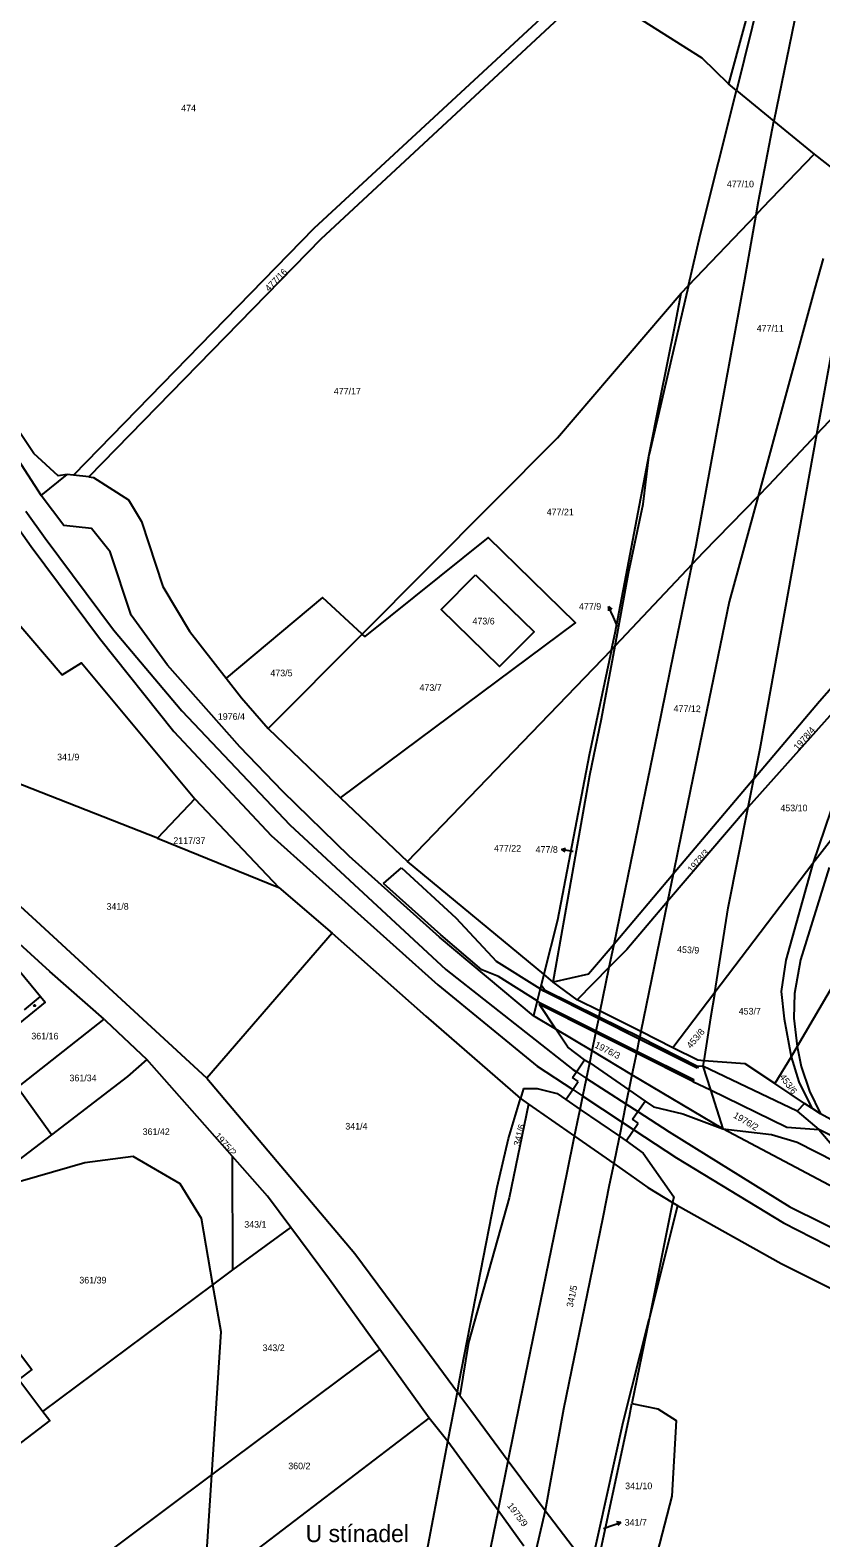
# Model space of a CAD drawing. Extents: x -679220 to -673243, y -1075091 to -1066557.
# Drawn here: x -675598.1 to -675395.3, y -1072555.7 to -1072169.3 of the extents above; entities that cross this region are included whole.
import ezdxf

# ---------------------------------------------------------------- set-up
doc = ezdxf.new("R2010")
doc.units = 0
for name, color, linetype in [('Hranice parcel', 7, 'Continuous'), ('Parcelní čísla', 7, 'Continuous'), ('Pop  PČ popisy', 7, 'Continuous'), ('Poz předměty', 7, 'Continuous'), ('Vnitřní kresba', 7, 'Continuous'), ('Značky budov', 7, 'Continuous')]:
    doc.layers.add(name, color=color, linetype=linetype)

msp = doc.modelspace()

# ---------------------------------------------------------------- linework, layer by layer
at = {"layer": 'Hranice parcel'}
for p, q in [((-675416.99, -1072184.77), (-675419.02, -1072183.11)), ((-675431.11, -1072236.72), (-675429.24, -1072234.77)), ((-675595.28, -1072288.62), (-675588.59, -1072283.25)), ((-675586.94, -1072283.42), (-675588.59, -1072283.25)), ((-675582.99, -1072283.84), (-675586.94, -1072283.42)), ((-675537.03, -1072348.31), (-675512.94, -1072324.1)), ((-675448.03, -1072327.12), (-675449.01, -1072328.16)), ((-675501.33, -1072382.38), (-675449.01, -1072328.16)), ((-675379.42, -1072329.8), (-675413.96, -1072368.46)), ((-675379.42, -1072329.8), (-675397.36, -1072382.87)), ((-675565.38, -1072376.43), (-675634.57, -1072349.32)), ((-675537.03, -1072348.31), (-675518.46, -1072366.07)), ((-675413.96, -1072368.46), (-675412.53, -1072361.24)), ((-675555.87, -1072366.37), (-675565.38, -1072376.43)), ((-675555.87, -1072366.37), (-675534.31, -1072389.02)), ((-675518.46, -1072366.07), (-675501.33, -1072382.38)), ((-675565.38, -1072376.43), (-675534.31, -1072389.02)), ((-675466.34, -1072411.3), (-675501.33, -1072382.38)), ((-675397.36, -1072382.87), (-675422.55, -1072416)), ((-675534.31, -1072389.02), (-675520.61, -1072400.73)), ((-675520.61, -1072400.73), (-675552.78, -1072437.9)), ((-675464, -1072413.32), (-675466.34, -1072411.3)), ((-675457.77, -1072417.82), (-675464, -1072413.32)), ((-675422.55, -1072416), (-675433.24, -1072430.14)), ((-675601.34, -1072440.3), (-675579.08, -1072422.85)), ((-675546.21, -1072458), (-675568.18, -1072433.16)), ((-675402.97, -1072432.45), (-675407.15, -1072439.33)), ((-675399.54, -1072444.38), (-675407.15, -1072439.33)), ((-675592.6, -1072452.44), (-675601.34, -1072440.3)), ((-675472.35, -1072443.11), (-675470.27, -1072444.57)), ((-675397.67, -1072445.61), (-675399.54, -1072444.38)), ((-675592.6, -1072452.44), (-675612.87, -1072467.95)), ((-675546.11, -1072487.08), (-675546.21, -1072458)), ((-675432.05, -1072470.56), (-675439.38, -1072499.72)), ((-675546.11, -1072487.08), (-675531.24, -1072476.19)), ((-675551.2, -1072490.89), (-675546.11, -1072487.08)), ((-675594.8, -1072523.34), (-675551.2, -1072490.89)), ((-675439.38, -1072499.72), (-675443.75, -1072521.35)), ((-675551.48, -1072539.61), (-675508.42, -1072507.49)), ((-675495.78, -1072525.1), (-675508.42, -1072507.49)), ((-675490.93, -1072531.03), (-675488.53, -1072518.4)), ((-675487.9, -1072519.25), (-675488.53, -1072518.4)), ((-675443.75, -1072521.35), (-675437.14, -1072522.7)), ((-675553.38, -1072569.02), (-675495.78, -1072525.1)), ((-675490.93, -1072531.03), (-675495.78, -1072525.1)), ((-675553.38, -1072569.02), (-675551.48, -1072539.61))]:
    msp.add_line(p, q, dxfattribs=at)
for points in [[(-675734.17, -1071838.14), (-675727.92, -1071869.06), (-675703.55, -1071993.04), (-675690.45, -1072058.85), (-675676.8, -1072118.37), (-675666.48, -1072149.75), (-675655.92, -1072177.48), (-675644.67, -1072202.06), (-675627.82, -1072234.57), (-675609.97, -1072265.91), (-675595.28, -1072288.62)], [(-675396.43, -1072100.9), (-675399.9, -1072112.67), (-675419.02, -1072183.11)], [(-675461.51, -1072161.01), (-675525.35, -1072220.15), (-675586.94, -1072283.42)], [(-675455.31, -1072159.46), (-675523.57, -1072222.93), (-675582.99, -1072283.84)], [(-675419.02, -1072183.11), (-675425.75, -1072176.54), (-675442.66, -1072165.78), (-675455.31, -1072159.46)], [(-675429.24, -1072234.77), (-675426.15, -1072221.5), (-675416.99, -1072184.77)], [(-675416.99, -1072184.77), (-675407.35, -1072192.65), (-675397.04, -1072201.08)], [(-675429.24, -1072234.77), (-675411.94, -1072216.66), (-675410.26, -1072214.9), (-675397.04, -1072201.08)], [(-675397.04, -1072201.08), (-675387.67, -1072208.44), (-675385.83, -1072210), (-675381.09, -1072214.03)], [(-675588.59, -1072283.25), (-675590.86, -1072283.57), (-675597.09, -1072277.84), (-675606.59, -1072263.7), (-675624.31, -1072232.74), (-675636.9, -1072208.76)], [(-675381.09, -1072214.03), (-675385.95, -1072219.83), (-675388.33, -1072228.27), (-675396.42, -1072272.96)], [(-675358.84, -1072232.94), (-675385.17, -1072261.11), (-675396.42, -1072272.96)], [(-675512.94, -1072324.1), (-675462.89, -1072273.79), (-675431.11, -1072236.72)], [(-675439.34, -1072278.05), (-675436.63, -1072264.33), (-675432.63, -1072244.42), (-675431.11, -1072236.72)], [(-675396.42, -1072272.96), (-675408.79, -1072286), (-675411.44, -1072288.72), (-675425.54, -1072303.22), (-675428.31, -1072306.15), (-675448.03, -1072327.12)], [(-675396.42, -1072272.96), (-675411, -1072353.53), (-675412.53, -1072361.24)], [(-675449.01, -1072328.16), (-675448.08, -1072323.76), (-675439.34, -1072278.05)], [(-675448.03, -1072327.12), (-675444.65, -1072308.47), (-675440.87, -1072290.79), (-675439.34, -1072278.05)], [(-675582.99, -1072283.84), (-675581.79, -1072283.97), (-675572.82, -1072289.71), (-675569.53, -1072295.25), (-675564.07, -1072311.9), (-675557.23, -1072323.34), (-675547.81, -1072335.42)], [(-675469.01, -1072421.97), (-675493.12, -1072401.8), (-675516.24, -1072381.02), (-675533.31, -1072364.43), (-675544.32, -1072352.97), (-675562.86, -1072332.04), (-675572.15, -1072319.29), (-675577.54, -1072303.06), (-675582.29, -1072297.06), (-675589.45, -1072296.26), (-675595.28, -1072288.62)], [(-675518.46, -1072366.07), (-675458.25, -1072321.24), (-675480.64, -1072299.39), (-675512.25, -1072324.74), (-675512.94, -1072324.1)], [(-675483.86, -1072308.92), (-675468.87, -1072323.55), (-675477.72, -1072332.44), (-675492.67, -1072317.81), (-675483.86, -1072308.92)], [(-675606.52, -1072315.16), (-675589.88, -1072334.57), (-675584.91, -1072331.48), (-675555.87, -1072366.37)], [(-675512.94, -1072324.1), (-675523.07, -1072314.75), (-675547.81, -1072335.42)], [(-675412.53, -1072361.24), (-675395.68, -1072341.32), (-675375.49, -1072318.41)], [(-675464, -1072413.32), (-675458.73, -1072383.94), (-675454.54, -1072360.24), (-675451.61, -1072345.79), (-675448.03, -1072327.12)], [(-675449.01, -1072328.16), (-675454.73, -1072355.18), (-675462.88, -1072397.47), (-675466.34, -1072411.3)], [(-675547.81, -1072335.42), (-675543.88, -1072340.45), (-675537.03, -1072348.31)], [(-675359.05, -1072336.81), (-675367.17, -1072346.12), (-675382.04, -1072363.17), (-675387.58, -1072370.29), (-675397.36, -1072382.87)], [(-675412.53, -1072361.24), (-675433.18, -1072385.64), (-675448.35, -1072403.57), (-675454.87, -1072411.28), (-675464, -1072413.32)], [(-675552.78, -1072437.9), (-675596.45, -1072397.73), (-675630.17, -1072366.89)], [(-675413.96, -1072368.46), (-675434.62, -1072392.65), (-675445.1, -1072404.93), (-675449.57, -1072409.47), (-675457.77, -1072417.82)], [(-675422.55, -1072416), (-675419.08, -1072394.3), (-675413.96, -1072368.46)], [(-675397.36, -1072382.87), (-675404.31, -1072407.7), (-675405.48, -1072415.72), (-675404.76, -1072422.71), (-675402.97, -1072432.45)], [(-675520.61, -1072400.73), (-675496.57, -1072422.06), (-675472.35, -1072443.11)], [(-675579.08, -1072422.85), (-675593.02, -1072410.6), (-675600.77, -1072403.5)], [(-675383.87, -1072402.76), (-675390.15, -1072411.15), (-675391.78, -1072413.33), (-675401.43, -1072429.83), (-675402.97, -1072432.45)], [(-675602.94, -1072425.54), (-675610.49, -1072416.34), (-675607.77, -1072414.09), (-675609.09, -1072412.5), (-675605.87, -1072409.85), (-675603.11, -1072407.59), (-675601.79, -1072409.24), (-675595.41, -1072416.98), (-675594.19, -1072418.46), (-675598.41, -1072421.88), (-675602.94, -1072425.54)], [(-675466.34, -1072411.3), (-675467.05, -1072414.13), (-675467.28, -1072415.07), (-675468.04, -1072418.11), (-675469.01, -1072421.97)], [(-675422.55, -1072416), (-675423.58, -1072422.44), (-675425.32, -1072433.45)], [(-675433.24, -1072430.14), (-675441.49, -1072426), (-675451.89, -1072420.77), (-675457.77, -1072417.82)], [(-675579.08, -1072422.85), (-675578.69, -1072423.2), (-675568.18, -1072433.16)], [(-675420.5, -1072450.92), (-675443.76, -1072437.04), (-675453.98, -1072430.94), (-675463.29, -1072425.38), (-675469.01, -1072421.97)], [(-675425.32, -1072433.45), (-675426.9, -1072433.33), (-675433.24, -1072430.14)], [(-675568.18, -1072433.16), (-675573.07, -1072437.5), (-675592.6, -1072452.44)], [(-675425.32, -1072433.45), (-675425.55, -1072434.88), (-675423.65, -1072440.93), (-675420.5, -1072450.92)], [(-675407.15, -1072439.33), (-675414.75, -1072434.28), (-675425.32, -1072433.45)], [(-675402.97, -1072432.45), (-675400.93, -1072438.84), (-675397.67, -1072445.61)], [(-675552.78, -1072437.9), (-675514.82, -1072482.88), (-675496.88, -1072507.03), (-675488.53, -1072518.4)], [(-675488.53, -1072518.4), (-675488.04, -1072515.8), (-675478.35, -1072465.86), (-675475.43, -1072453.36), (-675472.35, -1072443.11)], [(-675470.27, -1072444.57), (-675475.25, -1072468.57), (-675485.69, -1072505.71), (-675487.9, -1072519.25)], [(-675470.27, -1072444.57), (-675458.46, -1072452.81), (-675448.42, -1072459.82), (-675439.69, -1072465.91), (-675433.33, -1072469.79), (-675432.05, -1072470.56)], [(-675399.54, -1072444.38), (-675401.42, -1072446.36), (-675395.88, -1072451.08), (-675386.77, -1072461.8), (-675376.04, -1072474.42)], [(-675368.49, -1072461.75), (-675395.42, -1072447.1), (-675397.67, -1072445.61)], [(-675376.04, -1072474.42), (-675393.22, -1072465.39), (-675420.5, -1072450.92)], [(-675551.2, -1072490.89), (-675554.17, -1072473.86), (-675559.59, -1072465.02), (-675571.66, -1072458.04), (-675584, -1072459.65), (-675612.87, -1072467.95)], [(-675531.24, -1072476.19), (-675537.19, -1072468.19), (-675546.21, -1072458)], [(-675432.05, -1072470.56), (-675405.5, -1072485.44), (-675369.37, -1072503.53), (-675276.78, -1072545.83)], [(-675508.42, -1072507.49), (-675521.3, -1072489.55), (-675531.24, -1072476.19)], [(-675667.06, -1072576), (-675695.35, -1072538.98), (-675624.32, -1072484.68), (-675612.98, -1072499.47), (-675609.59, -1072496.88), (-675597.62, -1072512.63), (-675601, -1072515.19), (-675594.8, -1072523.34)], [(-675551.48, -1072539.61), (-675549.11, -1072502.92), (-675551.2, -1072490.89)], [(-675454.36, -1072563.91), (-675446, -1072526.06), (-675439.38, -1072499.72)], [(-675487.9, -1072519.25), (-675485.11, -1072523), (-675475.5, -1072535.97), (-675466.02, -1072548.77), (-675454.36, -1072563.91)], [(-675594.8, -1072523.34), (-675593.03, -1072525.66), (-675664.03, -1072579.96), (-675667.06, -1072576)], [(-675453.16, -1072565.56), (-675444.4, -1072524.55), (-675443.75, -1072521.35)], [(-675437.14, -1072522.7), (-675432.4, -1072525.63), (-675433.53, -1072545.05), (-675440.45, -1072571.81)], [(-675499.44, -1072577.56), (-675497.51, -1072565.78), (-675490.93, -1072531.03)], [(-675471.44, -1072557.92), (-675478.09, -1072548.74), (-675490.93, -1072531.03)], [(-675681.36, -1072633.74), (-675619.75, -1072590.56), (-675551.48, -1072539.61)]]:
    msp.add_lwpolyline(points, dxfattribs=at)
at = {"layer": 'Pop  PČ popisy'}
for p, q in [((-675449.75, -1072317.03), (-675449.8, -1072318.15)), ((-675448.53, -1072319.77), (-675449.75, -1072317.03)), ((-675449.75, -1072317.03), (-675448.89, -1072317.74)), ((-675447.47, -1072322.18), (-675448.53, -1072319.77)), ((-675461.85, -1072379.29), (-675460.77, -1072378.97)), ((-675458.89, -1072379.81), (-675461.85, -1072379.29)), ((-675461.85, -1072379.29), (-675460.95, -1072379.96)), ((-675458.79, -1072379.83), (-675458.89, -1072379.81)), ((-675451.04, -1072553.34), (-675449.45, -1072552.78)), ((-675449.45, -1072552.78), (-675446.61, -1072551.8)), ((-675446.61, -1072551.8), (-675447.72, -1072551.66)), ((-675446.61, -1072551.8), (-675447.4, -1072552.6))]:
    msp.add_line(p, q, dxfattribs=at)
at = {"layer": 'Poz předměty'}
for p, q in [((-675599.13, -1072292.63), (-675594.24, -1072299.49)), ((-675602.52, -1072295), (-675597.79, -1072301.64)), ((-675594.24, -1072299.49), (-675576.68, -1072323.01)), ((-675597.79, -1072301.64), (-675580.26, -1072325.16)), ((-675576.68, -1072323.01), (-675559.15, -1072343.77)), ((-675580.26, -1072325.16), (-675561.19, -1072349.1)), ((-675559.15, -1072343.77), (-675531.47, -1072373)), ((-675561.19, -1072349.1), (-675536.28, -1072375.75)), ((-675531.47, -1072373), (-675491.51, -1072410.05)), ((-675536.28, -1072375.75), (-675493.56, -1072414.04)), ((-675491.51, -1072410.05), (-675458.95, -1072435.72)), ((-675493.56, -1072414.04), (-675468.02, -1072434.83)), ((-675468.02, -1072434.83), (-675458.94, -1072440.83)), ((-675458.95, -1072435.72), (-675458.02, -1072436.32)), ((-675458.02, -1072436.32), (-675455.42, -1072438)), ((-675455.42, -1072438), (-675445.3, -1072444.54)), ((-675458.94, -1072440.83), (-675456.35, -1072442.53)), ((-675456.35, -1072442.53), (-675446.25, -1072449.2)), ((-675445.3, -1072444.54), (-675442.26, -1072446.51)), ((-675442.26, -1072446.51), (-675434.21, -1072451.71)), ((-675446.25, -1072449.2), (-675443.31, -1072451.13)), ((-675443.31, -1072451.13), (-675432.34, -1072458.38)), ((-675434.21, -1072451.71), (-675403.24, -1072470.9)), ((-675432.34, -1072458.38), (-675404.93, -1072474.99)), ((-675403.24, -1072470.9), (-675324.84, -1072509.99)), ((-675404.93, -1072474.99), (-675330.45, -1072513.19))]:
    msp.add_line(p, q, dxfattribs=at)
at = {"layer": 'Vnitřní kresba'}
for p, q in [((-675399, -1072112.58), (-675416.99, -1072184.77)), ((-675399.58, -1072154.53), (-675407.35, -1072192.65)), ((-675411.32, -1072213.13), (-675407.35, -1072192.65)), ((-675411.94, -1072216.66), (-675411.32, -1072213.13)), ((-675414.85, -1072233.18), (-675411.94, -1072216.66)), ((-675394.71, -1072227.86), (-675396.91, -1072235.45)), ((-675427.32, -1072301.33), (-675414.85, -1072233.18)), ((-675429.24, -1072234.77), (-675439.34, -1072278.05)), ((-675396.91, -1072235.45), (-675411.44, -1072288.72)), ((-675411.44, -1072288.72), (-675418.84, -1072315.87)), ((-675428.31, -1072306.15), (-675427.32, -1072301.33)), ((-675432.98, -1072328.92), (-675428.31, -1072306.15)), ((-675418.84, -1072315.87), (-675425.73, -1072349.44)), ((-675437.16, -1072349.09), (-675432.98, -1072328.92)), ((-675444.05, -1072382.78), (-675437.16, -1072349.09)), ((-675425.73, -1072349.44), (-675431.88, -1072379.33)), ((-675431.88, -1072379.33), (-675433.18, -1072385.64)), ((-675507.46, -1072388), (-675502.82, -1072384.03)), ((-675502.82, -1072384.03), (-675488.92, -1072396.87)), ((-675448.35, -1072403.57), (-675444.05, -1072382.78)), ((-675393.18, -1072383.9), (-675400.55, -1072407.56)), ((-675492.75, -1072401.23), (-675507.46, -1072388)), ((-675433.18, -1072385.64), (-675434.62, -1072392.65)), ((-675434.62, -1072392.65), (-675437.36, -1072406.01)), ((-675488.92, -1072396.87), (-675478.49, -1072408.04)), ((-675482.28, -1072410.14), (-675492.75, -1072401.23)), ((-675449.57, -1072409.47), (-675448.35, -1072403.57)), ((-675467.28, -1072415.07), (-675478.49, -1072408.04)), ((-675437.36, -1072406.01), (-675441.49, -1072426)), ((-675400.55, -1072407.56), (-675402.09, -1072416.19)), ((-675477.97, -1072411.89), (-675482.28, -1072410.14)), ((-675468.04, -1072418.11), (-675477.97, -1072411.89)), ((-675451.89, -1072420.77), (-675449.65, -1072409.88)), ((-675449.65, -1072409.88), (-675449.57, -1072409.47)), ((-675466.34, -1072415.66), (-675467.28, -1072415.07)), ((-675466.14, -1072415.27), (-675467.05, -1072414.13)), ((-675466.34, -1072415.66), (-675466.14, -1072415.27)), ((-675452.29, -1072422.71), (-675466.34, -1072415.66)), ((-675466.14, -1072415.27), (-675452.19, -1072422.24)), ((-675402.09, -1072416.19), (-675402.24, -1072422.54)), ((-675599.55, -1072420.42), (-675595.41, -1072416.98)), ((-675467.27, -1072418.6), (-675468.04, -1072418.11)), ((-675467.49, -1072419.04), (-675467.27, -1072418.6)), ((-675463.29, -1072425.38), (-675467.49, -1072419.04)), ((-675453.02, -1072426.28), (-675467.49, -1072419.04)), ((-675467.27, -1072418.6), (-675452.92, -1072425.79)), ((-675452.92, -1072425.79), (-675452.29, -1072422.71)), ((-675452.29, -1072422.71), (-675452.19, -1072422.24)), ((-675441.89, -1072427.93), (-675452.29, -1072422.71)), ((-675452.19, -1072422.24), (-675451.89, -1072420.77)), ((-675452.19, -1072422.24), (-675441.76, -1072427.31)), ((-675402.24, -1072422.54), (-675401.43, -1072429.83)), ((-675460.23, -1072430.01), (-675463.29, -1072425.38)), ((-675453.98, -1072430.94), (-675453.02, -1072426.28)), ((-675453.02, -1072426.28), (-675452.92, -1072425.79)), ((-675442.62, -1072431.49), (-675453.02, -1072426.28)), ((-675452.92, -1072425.79), (-675442.52, -1072431)), ((-675441.76, -1072427.31), (-675441.89, -1072427.93)), ((-675441.49, -1072426), (-675441.76, -1072427.31)), ((-675441.76, -1072427.31), (-675426.81, -1072434.93)), ((-675455.9, -1072433.21), (-675460.23, -1072430.01)), ((-675454.6, -1072433.96), (-675453.98, -1072430.94)), ((-675442.62, -1072431.49), (-675443.76, -1072437.04)), ((-675442.52, -1072431), (-675442.62, -1072431.49)), ((-675428.13, -1072438.75), (-675442.62, -1072431.49)), ((-675441.89, -1072427.93), (-675442.52, -1072431)), ((-675442.52, -1072431), (-675427.92, -1072438.31)), ((-675427.06, -1072435.38), (-675441.89, -1072427.93)), ((-675401.43, -1072429.83), (-675400.37, -1072434.91)), ((-675458.02, -1072436.32), (-675455.9, -1072433.21)), ((-675455.9, -1072433.21), (-675454.6, -1072433.96)), ((-675455.42, -1072438), (-675454.6, -1072433.96)), ((-675454.6, -1072433.96), (-675444.57, -1072440.95)), ((-675426.81, -1072434.93), (-675427.06, -1072435.38)), ((-675425.55, -1072434.88), (-675426.81, -1072434.93)), ((-675401.42, -1072446.36), (-675425.55, -1072434.88)), ((-675400.37, -1072434.91), (-675398.26, -1072441.3)), ((-675459, -1072437.75), (-675458.02, -1072436.32)), ((-675457.55, -1072438.82), (-675459, -1072437.75)), ((-675458.94, -1072440.83), (-675457.55, -1072438.82)), ((-675456.35, -1072442.53), (-675455.42, -1072438)), ((-675443.76, -1072437.04), (-675444.57, -1072440.95)), ((-675427.92, -1072438.31), (-675428.13, -1072438.75)), ((-675428.13, -1072438.75), (-675423.65, -1072440.93)), ((-675471.6, -1072440.61), (-675472.35, -1072443.11)), ((-675471.6, -1072440.61), (-675468.1, -1072440.56)), ((-675468.1, -1072440.56), (-675462.97, -1072441.88)), ((-675462.97, -1072441.88), (-675460.71, -1072443.39)), ((-675460.71, -1072443.39), (-675458.94, -1072440.83)), ((-675457.04, -1072445.92), (-675456.35, -1072442.53)), ((-675444.8, -1072442.07), (-675445.3, -1072444.54)), ((-675444.57, -1072440.95), (-675444.8, -1072442.07)), ((-675444.57, -1072440.95), (-675440.41, -1072443.84)), ((-675423.65, -1072440.93), (-675404.06, -1072450.45)), ((-675398.26, -1072441.3), (-675395.42, -1072447.1)), ((-675460.71, -1072443.39), (-675457.04, -1072445.92)), ((-675457.37, -1072447.53), (-675457.04, -1072445.92)), ((-675457.04, -1072445.92), (-675446.99, -1072452.83)), ((-675445.3, -1072444.54), (-675446.99, -1072452.83)), ((-675443.6, -1072448.45), (-675442.26, -1072446.51)), ((-675442.26, -1072446.51), (-675440.41, -1072443.84)), ((-675440.41, -1072443.84), (-675438.25, -1072445.3)), ((-675438.25, -1072445.3), (-675430.71, -1072447.1)), ((-675430.71, -1072447.1), (-675420.5, -1072450.92)), ((-675458.46, -1072452.81), (-675457.37, -1072447.53)), ((-675445.28, -1072454.01), (-675442.15, -1072449.43)), ((-675442.15, -1072449.43), (-675443.6, -1072448.45)), ((-675420.5, -1072450.92), (-675407.97, -1072452.39)), ((-675404.06, -1072450.45), (-675395.88, -1072451.08)), ((-675460.39, -1072462.12), (-675458.46, -1072452.81)), ((-675447.14, -1072453.56), (-675448.42, -1072459.82)), ((-675446.99, -1072452.83), (-675447.14, -1072453.56)), ((-675446.99, -1072452.83), (-675445.28, -1072454.01)), ((-675445.28, -1072454.01), (-675440.92, -1072457.16)), ((-675407.97, -1072452.39), (-675401.4, -1072454.31)), ((-675401.4, -1072454.31), (-675386.77, -1072461.8)), ((-675236.54, -1072532.18), (-675395.88, -1072451.08)), ((-675440.92, -1072457.16), (-675433.03, -1072468.32)), ((-675465.09, -1072485), (-675460.39, -1072462.12)), ((-675448.42, -1072459.82), (-675449.56, -1072465.35)), ((-675449.56, -1072465.35), (-675451.26, -1072473.62)), ((-675433.33, -1072469.79), (-675439.38, -1072499.72)), ((-675433.03, -1072468.32), (-675433.33, -1072469.79)), ((-675451.26, -1072473.62), (-675461.35, -1072522.75)), ((-675472.41, -1072520.76), (-675465.09, -1072485)), ((-675475.5, -1072535.97), (-675472.41, -1072520.76)), ((-675461.35, -1072522.75), (-675466.02, -1072548.77)), ((-675478.09, -1072548.74), (-675475.5, -1072535.97)), ((-675478.09, -1072548.74), (-675481.29, -1072564.52)), ((-675466.02, -1072548.77), (-675468.88, -1072561.25))]:
    msp.add_line(p, q, dxfattribs=at)
at = {"layer": 'Značky budov'}
msp.add_circle((-675596.93, -1072419.34), 0.175, dxfattribs=at)

# ---------------------------------------------------------------- texts
at = {"layer": 'Parcelní čísla'}
for s, p in [('474', (-675559.34, -1072190.16)), ('477/10', (-675419.43, -1072209.6)), ('477/11', (-675411.77, -1072246.59)), ('477/17', (-675520.2, -1072262.7)), ('477/21', (-675465.62, -1072293.67)), ('477/9', (-675457.34, -1072317.87)), ('473/6', (-675484.65, -1072321.64)), ('473/5', (-675536.47, -1072334.94)), ('473/7', (-675498.23, -1072338.65)), ('1976/4', (-675549.94, -1072346.08)), ('341/9', (-675591.14, -1072356.48)), ('453/10', (-675405.7, -1072369.52)), ('2117/37', (-675561.35, -1072377.89)), ('477/22', (-675479.13, -1072379.86)), ('477/8', (-675468.46, -1072380.16)), ('341/8', (-675578.49, -1072394.76)), ('453/7', (-675416.39, -1072421.62)), ('361/16', (-675597.76, -1072428)), ('361/34', (-675587.98, -1072438.73)), ('361/42', (-675569.22, -1072452.49)), ('341/4', (-675517.25, -1072451.1)), ('343/1', (-675543.16, -1072476.26)), ('361/39', (-675585.45, -1072490.55)), ('343/2', (-675538.49, -1072507.89)), ('360/2', (-675531.88, -1072538.16)), ('341/10', (-675445.5, -1072543.28)), ('341/7', (-675445.62, -1072552.64))]:
    msp.add_text(s, height=1.7, dxfattribs=at).set_placement(p)
for s, rotation, p in [('477/16', 46, (-675536.82, -1072236.44)), ('477/12', 359, (-675433.09, -1072344.01)), ('1978/4', 49, (-675401.2, -1072354.05)), ('1978/3', 48, (-675428.45, -1072385.4)), ('453/9', 357, (-675432.23, -1072405.73)), ('453/8', 50, (-675428.63, -1072430.46)), ('1976/3', 333, (-675453.49, -1072429.96)), ('453/6', 306, (-675405.99, -1072437.62)), ('1976/2', 329, (-675417.94, -1072447.9)), ('341/6', 76, (-675472.51, -1072455.46)), ('1975/2', 312, (-675550.91, -1072452.82)), ('341/5', 78, (-675458.93, -1072496.79)), ('1975/9', 307, (-675475.86, -1072547.54))]:
    msp.add_text(s, height=1.7, rotation=rotation, dxfattribs=at).set_placement(p)
at = {"layer": 'Pop  PČ popisy'}
msp.add_text('U stínadel', height=4.4, dxfattribs=at).set_placement((-675527.43, -1072556.84))

doc.saveas('drawing.dxf')
